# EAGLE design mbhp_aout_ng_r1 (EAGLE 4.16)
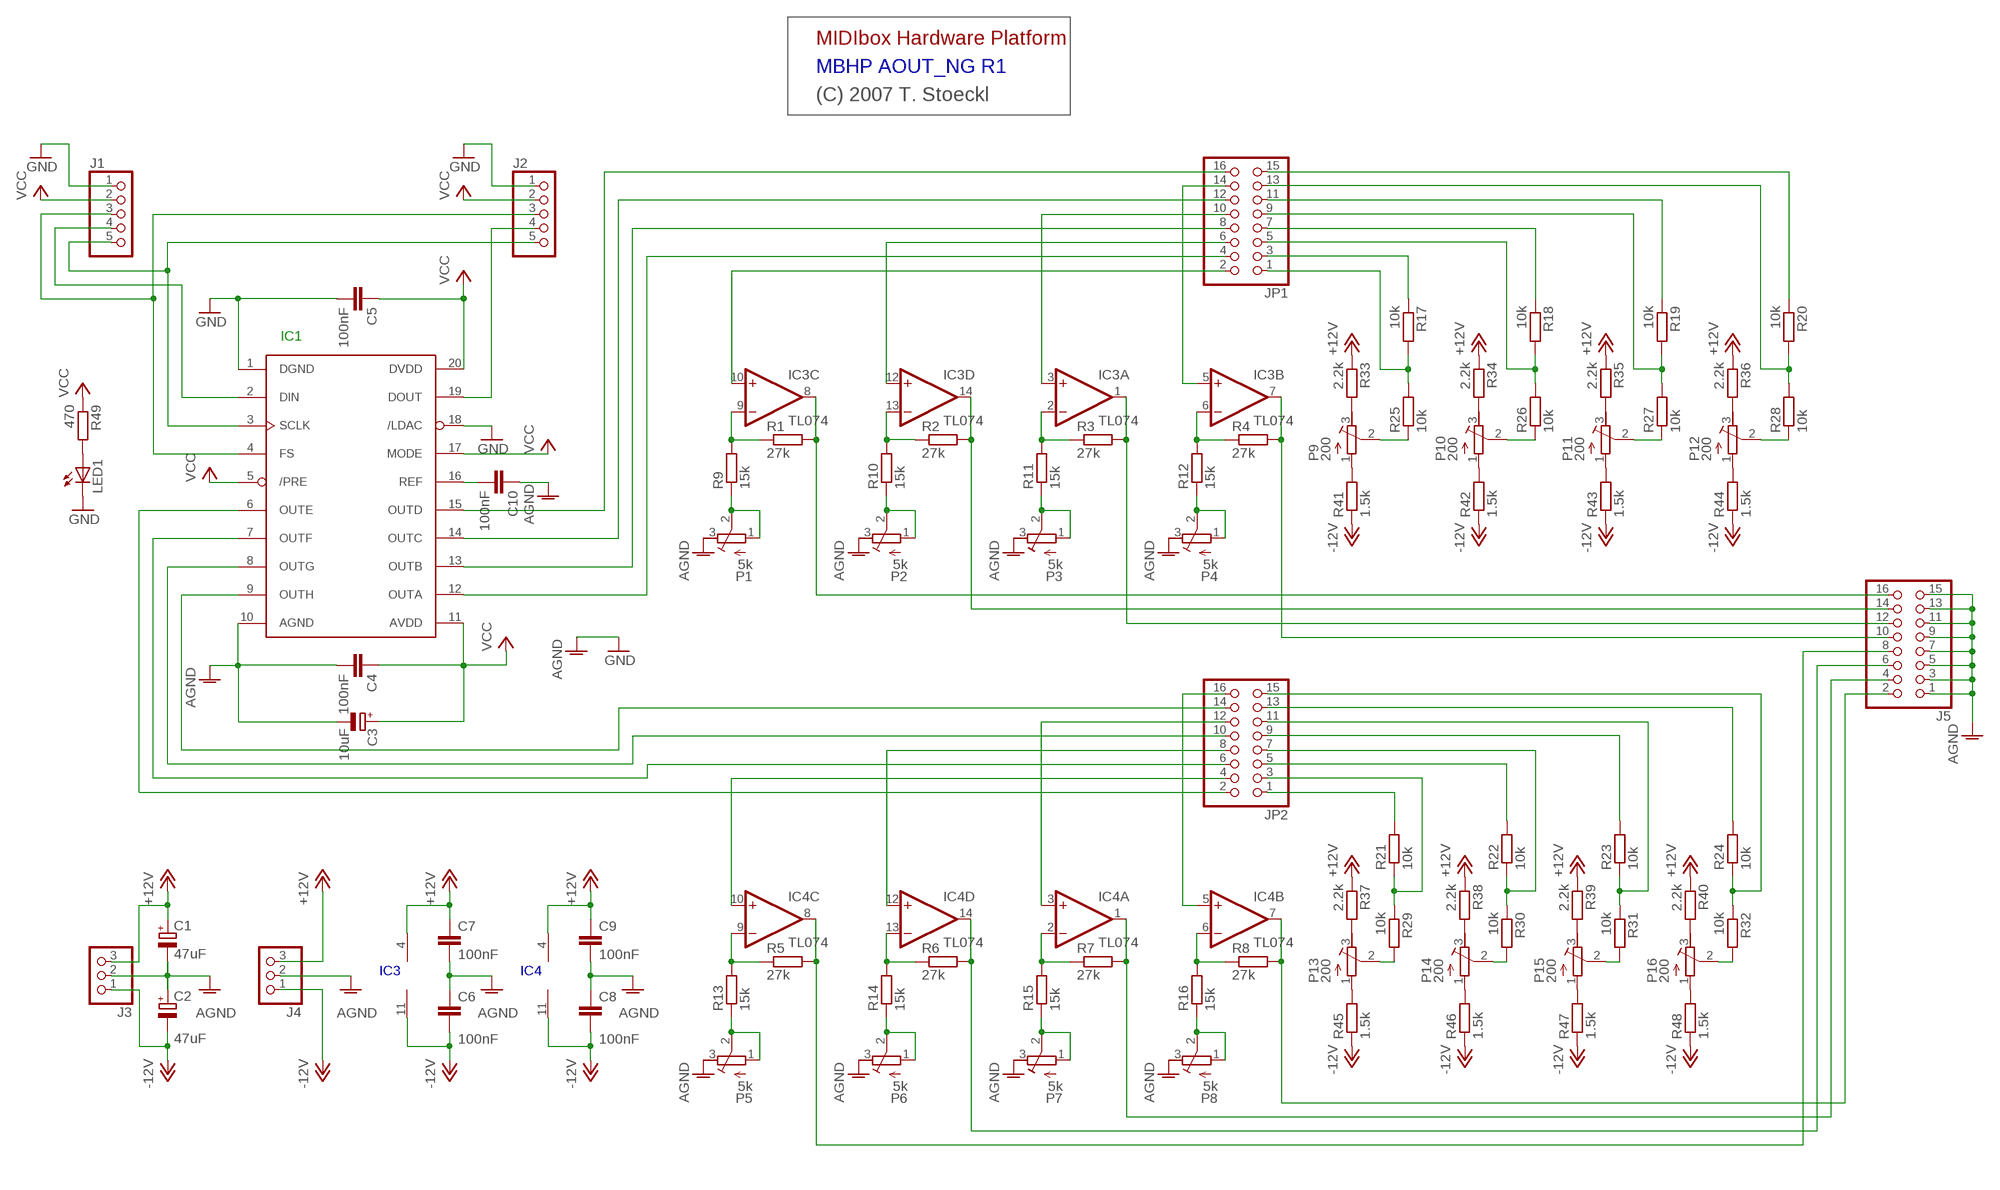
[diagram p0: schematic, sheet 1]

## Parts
C1  47uF  CPOL-EUE2-5  [E2-5]
C2  47uF  CPOL-EUE2-5  [E2-5]
C3  10uF  CPOL-EUE2.5-5  [E2,5-5]
C4  100nF  C2.5/2  [C2.5-2]
C5  100nF  C2.5/2  [C2.5-2]
C6  100nF  C2.5/2  [C2.5-2]
C7  100nF  C2.5/2  [C2.5-2]
C8  100nF  C2.5/2  [C2.5-2]
C9  100nF  C2.5/2  [C2.5-2]
C10  100nF  C2.5/2  [C2.5-2]
IC1  TLV5630  [SO20W]
IC3  TL074  TL074P  [DIL14]
IC4  TL074  TL074P  [DIL14]
J1  PINHD-1X5  [1X05]
J2  PINHD-1X5  [1X05]
J3  PINHD-1X3  [1X03]
J4  PINHD-1X3  [1X03]
J5  PINHD-2X8  [2X08]
JP1  PINHD-2X8  [2X08]
JP2  PINHD-2X8  [2X08]
LED1  LED3MM  [LED3MM]
P1  5k  R-TRIMM64Y  [RTRIM64Y]
P2  5k  R-TRIMM64Y  [RTRIM64Y]
P3  5k  R-TRIMM64Y  [RTRIM64Y]
P4  5k  R-TRIMM64Y  [RTRIM64Y]
P5  5k  R-TRIMM64Y  [RTRIM64Y]
P6  5k  R-TRIMM64Y  [RTRIM64Y]
P7  5k  R-TRIMM64Y  [RTRIM64Y]
P8  5k  R-TRIMM64Y  [RTRIM64Y]
P9  200  R-TRIMM64Y  [RTRIM64Y]
P10  200  R-TRIMM64Y  [RTRIM64Y]
P11  200  R-TRIMM64Y  [RTRIM64Y]
P12  200  R-TRIMM64Y  [RTRIM64Y]
P13  200  R-TRIMM64Y  [RTRIM64Y]
P14  200  R-TRIMM64Y  [RTRIM64Y]
P15  200  R-TRIMM64Y  [RTRIM64Y]
P16  200  R-TRIMM64Y  [RTRIM64Y]
R1  27k  R-EU_0207/2V  [0207/2V]
R2  27k  R-EU_0207/2V  [0207/2V]
R3  27k  R-EU_0207/2V  [0207/2V]
R4  27k  R-EU_0207/2V  [0207/2V]
R5  27k  R-EU_0207/2V  [0207/2V]
R6  27k  R-EU_0207/2V  [0207/2V]
R7  27k  R-EU_0207/2V  [0207/2V]
R8  27k  R-EU_0207/2V  [0207/2V]
R9  15k  R-EU_0207/2V  [0207/2V]
R10  15k  R-EU_0207/2V  [0207/2V]
R11  15k  R-EU_0207/2V  [0207/2V]
R12  15k  R-EU_0207/2V  [0207/2V]
R13  15k  R-EU_0207/2V  [0207/2V]
R14  15k  R-EU_0207/2V  [0207/2V]
R15  15k  R-EU_0207/2V  [0207/2V]
R16  15k  R-EU_0207/2V  [0207/2V]
R17  10k  R-EU_0207/2V  [0207/2V]
R18  10k  R-EU_0207/2V  [0207/2V]
R19  10k  R-EU_0207/2V  [0207/2V]
R20  10k  R-EU_0207/2V  [0207/2V]
R21  10k  R-EU_0207/2V  [0207/2V]
R22  10k  R-EU_0207/2V  [0207/2V]
R23  10k  R-EU_0207/2V  [0207/2V]
R24  10k  R-EU_0207/2V  [0207/2V]
R25  10k  R-EU_0207/2V  [0207/2V]
R26  10k  R-EU_0207/2V  [0207/2V]
R27  10k  R-EU_0207/2V  [0207/2V]
R28  10k  R-EU_0207/2V  [0207/2V]
R29  10k  R-EU_0207/2V  [0207/2V]
R30  10k  R-EU_0207/2V  [0207/2V]
R31  10k  R-EU_0207/2V  [0207/2V]
R32  10k  R-EU_0207/2V  [0207/2V]
R33  2.2k  R-EU_0207/2V  [0207/2V]
R34  2.2k  R-EU_0207/2V  [0207/2V]
R35  2.2k  R-EU_0207/2V  [0207/2V]
R36  2.2k  R-EU_0207/2V  [0207/2V]
R37  2.2k  R-EU_0207/2V  [0207/2V]
R38  2.2k  R-EU_0207/2V  [0207/2V]
R39  2.2k  R-EU_0207/2V  [0207/2V]
R40  2.2k  R-EU_0207/2V  [0207/2V]
R41  1.5k  R-EU_0207/2V  [0207/2V]
R42  1.5k  R-EU_0207/2V  [0207/2V]
R43  1.5k  R-EU_0207/2V  [0207/2V]
R44  1.5k  R-EU_0207/2V  [0207/2V]
R45  1.5k  R-EU_0207/2V  [0207/2V]
R46  1.5k  R-EU_0207/2V  [0207/2V]
R47  1.5k  R-EU_0207/2V  [0207/2V]
R48  1.5k  R-EU_0207/2V  [0207/2V]
R49  470  R-EU_0207/7  [0207/7]

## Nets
+12V: C1.+ C7.1 C9.1 IC3.4(P:V+) IC4.4(P:V+) J3.3 J4.3 R33.1 R34.1 R35.1 R36.1 R37.1 R38.1 R39.1 R40.1
-12V: C2.- C6.2 C8.2 IC3.11(P:V-) IC4.11(P:V-) J3.1 J4.1 R41.1 R42.1 R43.1 R44.1 R45.1 R46.1 R47.1 R48.1
AGND: C1.- C2.+ C3.- C4.2 C6.1 C7.2 C8.1 C9.2 C10.1 IC1.10(AGND) J3.2 J4.2 J5.1 J5.3 J5.5 J5.7 J5.9 J5.11 J5.13 J5.15 P1.3(A) P2.3(A) P3.3(A) P4.3(A) P5.3(A) P6.3(A) P7.3(A) P8.3(A)
GND: C5.2 IC1.1(DGND) IC1.18(/LDAC) J1.1 J2.1 LED1.K(C) ; supply symbol labelled AGND
N$1: JP1.3 R17.1
N$2: IC3.13(D:-IN) R2.1 R10.2
N$3: IC3.9(C:-IN) R1.1 R9.2
N$4: P9.1(E) R41.2
N$5: IC3.6(B:-IN) R4.1 R12.2
N$6: IC3.8(C:OUT) J5.16 R1.2
N$7: IC3.2(A:-IN) R3.1 R11.2
N$8: IC3.14(D:OUT) J5.14 R2.2
N$9: IC4.9(C:-IN) R5.1 R13.2
N$10: IC4.8(C:OUT) J5.8 R5.2
N$11: IC4.13(D:-IN) R6.1 R14.2
N$12: IC4.14(D:OUT) J5.6 R6.2
N$13: IC4.6(B:-IN) R8.1 R16.2
N$14: IC3.1(A:OUT) J5.12 R3.2
N$15: IC4.2(A:-IN) R7.1 R15.2
N$16: IC3.7(B:OUT) J5.10 R4.2
N$17: P2.1(E) P2.2(S) R10.1
N$18: P1.1(E) P1.2(S) R9.1
N$19: P4.1(E) P4.2(S) R12.1
N$20: P3.1(E) P3.2(S) R11.1
N$21: P5.1(E) P5.2(S) R13.1
N$22: P6.1(E) P6.2(S) R14.1
N$23: P8.1(E) P8.2(S) R16.1
N$24: P7.1(E) P7.2(S) R15.1
N$25: IC4.5(B:+IN) JP2.16
N$26: JP2.13 R24.2
N$27: JP2.15 R24.1 R32.1
N$28: P16.2(S) R32.2
N$29: IC1.12(OUTA) JP1.4
N$30: IC1.13(OUTB) JP1.8
N$31: IC4.3(A:+IN) JP2.12
N$32: JP2.9 R23.2
N$33: JP2.11 R23.1 R31.1
N$34: P15.2(S) R31.2
N$35: IC1.3(SCLK) J1.5 J2.5
N$36: IC4.12(D:+IN) JP2.8
N$37: JP2.5 R22.2
N$38: JP2.7 R22.1 R30.1
N$39: P14.2(S) R30.2
N$40: IC1.14(OUTC) JP1.12
N$41: IC4.10(C:+IN) JP2.4
N$42: JP2.3 R21.1 R29.1
N$43: P14.1(E) R46.2
N$44: P13.1(E) R45.2
N$45: IC1.15(OUTD) JP1.16
N$46: IC3.5(B:+IN) JP1.14
N$47: JP1.15 R20.1
N$48: JP1.13 R20.2 R28.2
N$49: P12.1(E) R44.2
N$50: IC1.6(OUTE) JP2.2
N$51: IC3.3(A:+IN) JP1.10
N$52: JP1.11 R19.1
N$53: JP1.9 R19.2 R27.2
N$54: P11.1(E) R43.2
N$56: IC3.12(D:+IN) JP1.6
N$57: JP1.7 R18.1
N$58: JP1.5 R18.2 R26.2
N$59: P10.2(S) R26.1
N$60: IC1.8(OUTG) JP2.10
N$61: IC3.10(C:+IN) JP1.2
N$62: JP2.1 R21.2
N$63: JP1.1 R17.2 R25.2
N$64: P9.2(S) R25.1
N$65: IC1.9(OUTH) JP2.14
N$66: IC1.2(DIN) J1.4
N$67: IC1.4(FS) J1.3 J2.3
N$68: P9.3(A) R33.2
N$69: IC4.7(B:OUT) J5.2 R8.2
N$70: IC4.1(A:OUT) J5.4 R7.2
N$71: P10.1(E) R42.2
N$72: P10.3(A) R34.2
N$73: P11.3(A) R35.2
N$74: P12.3(A) R36.2
N$75: P11.2(S) R27.1
N$76: IC1.19(DOUT) J2.4
N$77: P12.2(S) R28.1
N$78: C10.2 IC1.16(REF)
N$79: P13.2(S) R29.2
N$80: P13.3(A) R37.2
N$81: IC1.7(OUTF) JP2.6
N$85: P14.3(A) R38.2
N$86: P15.1(E) R47.2
N$87: P15.3(A) R39.2
N$88: P16.1(E) R48.2
N$89: P16.3(A) R40.2
N$95: LED1.A R49.2
VCC: C3.+ C4.1 C5.1 IC1.5(/PRE) IC1.11(AVDD) IC1.17(MODE) IC1.20(DVDD) J1.2 J2.2 R49.1

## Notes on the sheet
- MIDIbox Hardware Platform
- MBHP AOUT_NG R1
- (C) 2007 T. Stoeckl
- IC1
- IC3 | IC4
- .

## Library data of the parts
C1-C3 = rcl:CPOL-EU: POLARIZED CAPACITOR, European symbol
C4-C10 = capacitor-wima:C: CAPACITOR
IC1 = EigeneSammlung:TLV5630
IC3 IC4 = linear:TL074: OP AMP
J1 J2 = pinhead:PINHD-1X5: PIN HEADER
J3 J4 = pinhead:PINHD-1X3: PIN HEADER
J5 JP1 JP2 = pinhead:PINHD-2X8: PIN HEADER
LED1 = led:LED: LED
P1-P16 = rcl:R-TRIMM: Trimm resistor
R1-R49 = rcl:R-EU_: RESISTOR, European symbol

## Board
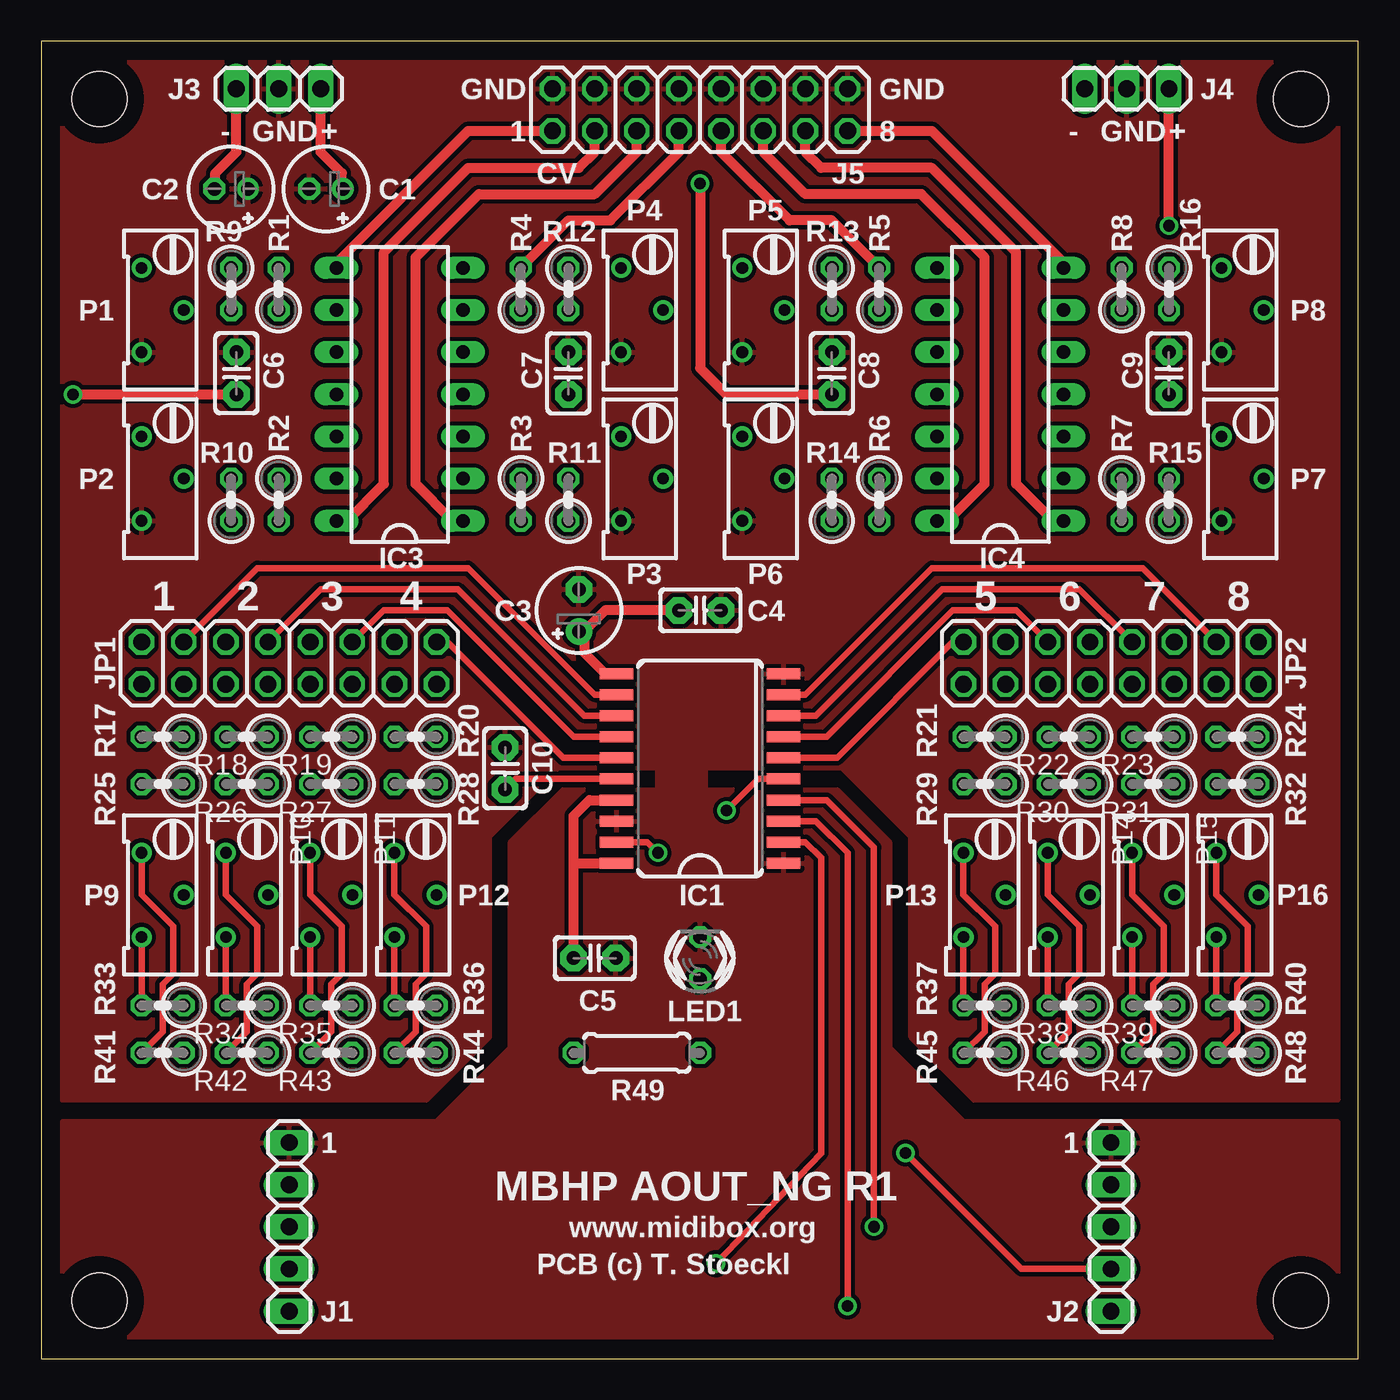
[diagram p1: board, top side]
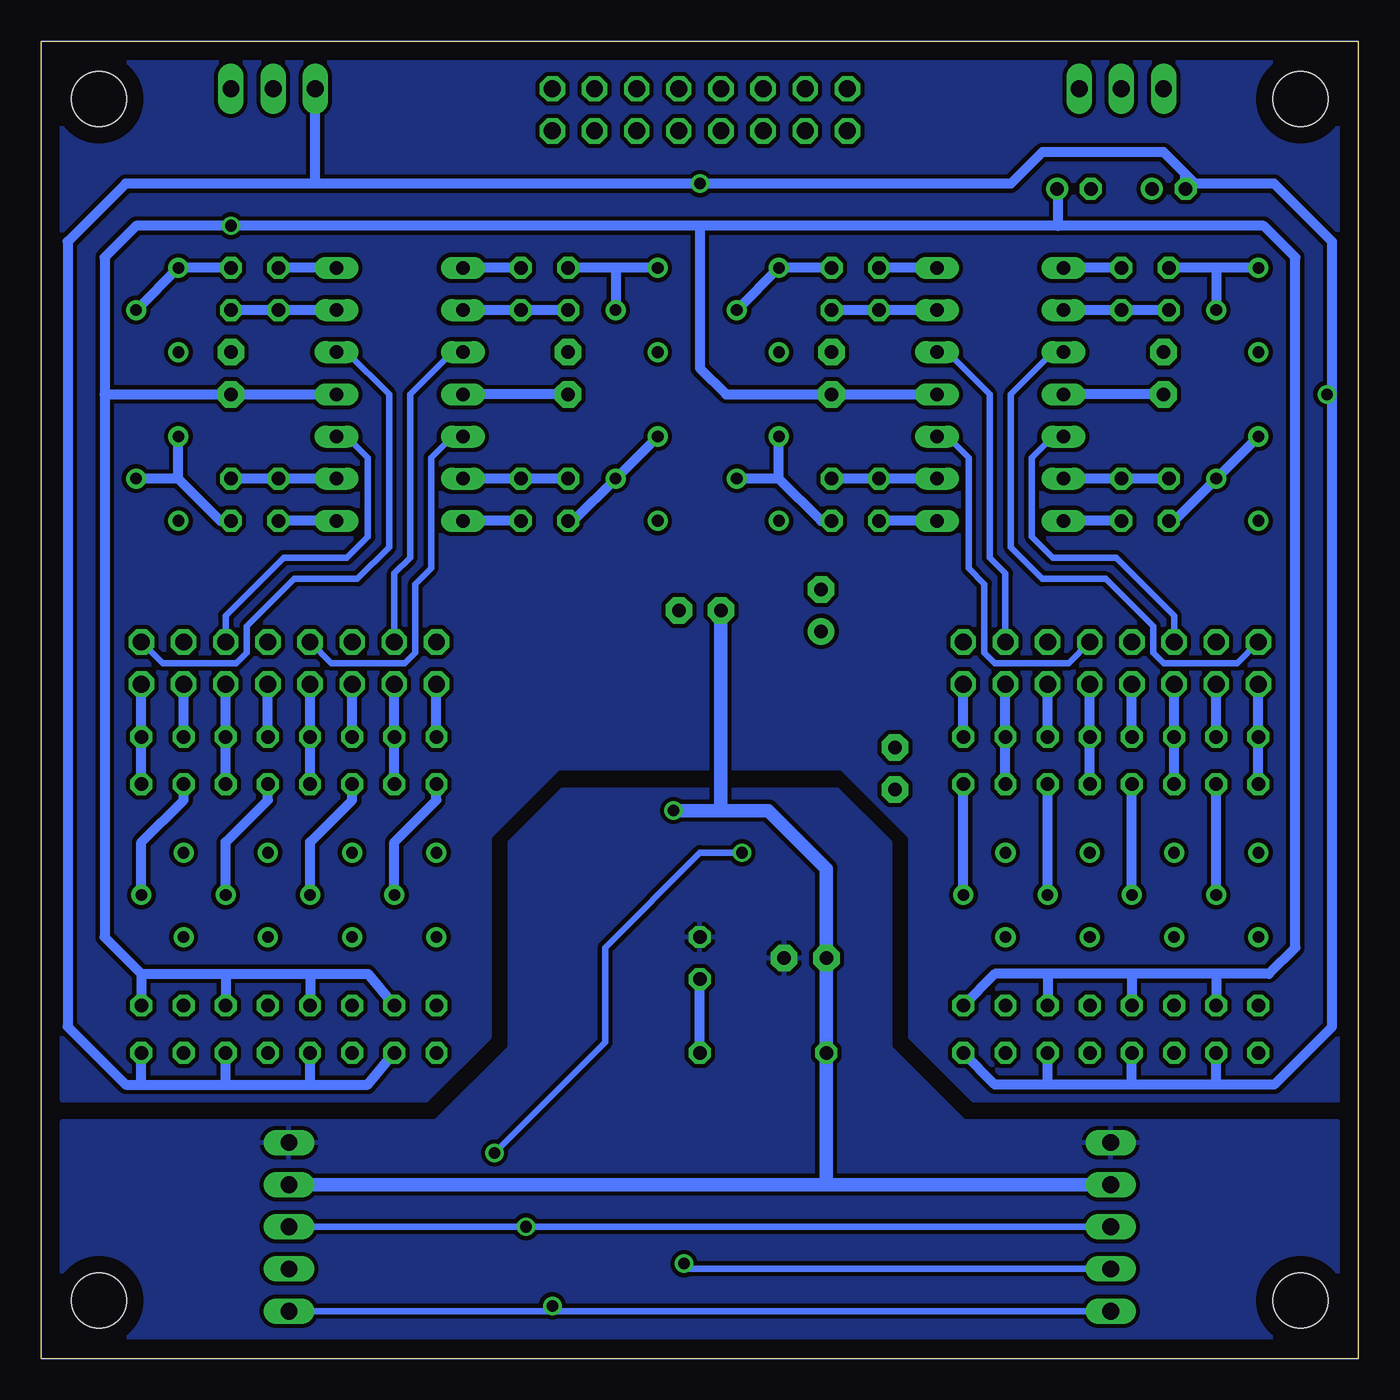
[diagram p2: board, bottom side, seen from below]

Size 79.36 x 79.37 mm. Coordinates in mm from the lower left corner, seen from the top.
Outline: 0,0 79.36,0 79.36,79.37 0,79.37 0,0
Copper layers (1*16): Top 0.035mm / dielectric 1.5mm / Bottom 0.035mm
Design rules "10mils": minimum track width 10mil, minimum drill 24mil, track to track 10mil, track to pad 10mil, pad to pad 10mil, via to via 10mil, smd to smd 10mil, copper to edge 40mil, drill to drill 10mil, minimum pad ring 10mil, minimum via ring 8mil, stop-mask expansion 0mil, vias tented up to drill 0mil, thermal gap 10mil
Holes 3.3 mm at 75.89,75.89 3.49,75.89 3.49,3.49 75.89,3.49

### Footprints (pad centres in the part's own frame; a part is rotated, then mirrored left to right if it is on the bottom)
E2-5 = drill 0.813 pad 1.27 round: + -1.016,0 | drill 0.813 pad 1.27 octagon: - 1.016,0
E2,5-5 = drill 0.813 pad 1.6 round: + -1.27,0 | drill 0.813 pad 1.6 octagon: - 1.27,0
C2.5-2 = drill 0.813 pad 1.6 octagon: 1 -1.27,0; 2 1.27,0
SO20W = smd 0.66 x 2.032: 1 -5.715,-5.029; 2 -4.445,-5.029; 3 -3.175,-5.029; 4 -1.905,-5.029; 5 -0.635,-5.029; 6 0.635,-5.029; 7 1.905,-5.029; 8 3.175,-5.029; 9 4.445,-5.029; 10 5.715,-5.029; 11 5.715,5.029; 12 4.445,5.029; 13 3.175,5.029; 14 1.905,5.029; 15 0.635,5.029; 16 -0.635,5.029; 17 -1.905,5.029; 18 -3.175,5.029; 19 -4.445,5.029; 20 -5.715,5.029
DIL14 = drill 0.813 long: 1 -7.62,-3.81; 2 -5.08,-3.81; 3 -2.54,-3.81; 4 0,-3.81; 5 2.54,-3.81; 6 5.08,-3.81; 7 7.62,-3.81; 8 7.62,3.81; 9 5.08,3.81; 10 2.54,3.81; 11 0,3.81; 12 -2.54,3.81; 13 -5.08,3.81; 14 -7.62,3.81
1X05 = drill 1.016 long: 1 -5.08,0; 2 -2.54,0; 3 0,0; 4 2.54,0; 5 5.08,0
1X03 = drill 1.016 long: 1 -2.54,0; 2 0,0; 3 2.54,0
2X08 = drill 1.016 octagon: 1 -8.89,-1.27; 2 -8.89,1.27; 3 -6.35,-1.27; 4 -6.35,1.27; 5 -3.81,-1.27; 6 -3.81,1.27; 7 -1.27,-1.27; 8 -1.27,1.27; 9 1.27,-1.27; 10 1.27,1.27; 11 3.81,-1.27; 12 3.81,1.27; 13 6.35,-1.27; 14 6.35,1.27; 15 8.89,-1.27; 16 8.89,1.27
LED3MM = drill 0.813 octagon: A -1.27,0; K 1.27,0
RTRIM64Y = drill 0.7 round: 1 0,-2.54; 2 -2.54,0; 3 0,2.54
0207/2V = drill 0.813 octagon: 1 -1.27,0; 2 1.27,0
0207/7 = drill 0.813 octagon: 1 -3.81,0; 2 3.81,0

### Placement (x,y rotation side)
C1  17.14,70.48 180 top
C2  11.43,70.48 180 top
C3  32.38,45.09 90 top
C4  39.69,45.09 0 top
C5  33.34,24.13 0 top
C6  11.75,59.37 270 top
C7  31.75,59.37 90 top
C8  47.62,59.37 270 top
C9  67.94,59.37 90 top
C10  27.94,35.56 270 top
IC1  39.69,35.56 90 top
IC3  21.59,58.1 90 top
IC4  57.78,58.1 90 top
J1  14.92,7.94 270 top
J2  64.45,7.94 270 top
J3  14.29,76.52 0 top
J4  65.41,76.52 0 top
J5  39.69,75.25 180 top
JP1  14.92,41.91 0 top
JP2  64.45,41.91 0 top
LED1  39.69,24.13 90 top
P1  6.03,63.18 180 top
P2  6.03,53.02 180 top
P3  34.92,53.02 180 top
P4  34.92,63.18 180 top
P5  42.23,63.18 180 top
P6  42.23,53.02 180 top
P7  71.12,53.02 180 top
P8  71.12,63.18 180 top
P9  6.03,27.94 180 top
P10  11.11,27.94 180 top
P11  16.19,27.94 180 top
P12  21.27,27.94 180 top
P13  55.56,27.94 180 top
P14  60.64,27.94 180 top
P15  65.72,27.94 180 top
P16  70.8,27.94 180 top
R1  14.29,64.45 90 top
R2  14.29,51.75 270 top
R3  28.89,51.75 270 top
R4  28.89,64.45 90 top
R5  50.48,64.45 90 top
R6  50.48,51.75 270 top
R7  65.09,51.75 270 top
R8  65.09,64.45 90 top
R9  11.43,64.45 270 top
R10  11.43,51.75 90 top
R11  31.75,51.75 90 top
R12  31.75,64.45 270 top
R13  47.62,64.45 270 top
R14  47.62,51.75 90 top
R15  67.94,51.75 90 top
R16  67.94,64.45 270 top
R17  7.3,37.47 180 top
R18  12.38,37.47 180 top
R19  17.46,37.47 180 top
R20  22.54,37.47 180 top
R21  56.83,37.47 180 top
R22  61.91,37.47 180 top
R23  66.99,37.47 180 top
R24  72.07,37.47 180 top
R25  7.3,34.61 180 top
R26  12.38,34.61 180 top
R27  17.46,34.61 180 top
R28  22.54,34.61 180 top
R29  56.83,34.61 180 top
R30  61.91,34.61 180 top
R31  66.99,34.61 180 top
R32  72.07,34.61 180 top
R33  7.3,21.27 180 top
R34  12.38,21.27 180 top
R35  17.46,21.27 180 top
R36  22.54,21.27 180 top
R37  56.83,21.27 180 top
R38  61.91,21.27 180 top
R39  66.99,21.27 180 top
R40  72.07,21.27 180 top
R41  7.3,18.41 180 top
R42  12.38,18.41 180 top
R43  17.46,18.41 180 top
R44  22.54,18.41 180 top
R45  56.83,18.41 180 top
R46  61.91,18.41 180 top
R47  66.99,18.41 180 top
R48  72.07,18.41 180 top
R49  35.88,18.41 0 top

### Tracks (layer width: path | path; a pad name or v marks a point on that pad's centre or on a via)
+12V  (via drill 0.7)
  Top 0.61: J3.3 16.83,72.71 18.1,71.44 18.1,70.48 C1.+ | v67.94,68.26 J4.3
  Bottom 0.61: 75.56,58.1 75.56,66.36 73.66,68.26 v67.94,68.26 39.69,68.26 | 75.56,58.1 C9.1 IC4.4 | 5.71,68.26 3.81,66.36 3.81,24.77 5.4,23.18 8.57,23.18 | 5.71,68.26 39.69,68.26 | 39.69,68.26 39.69,59.69 38.1,58.1 C7.1 IC3.4 | 8.57,23.18 13.65,23.18 | 13.65,23.18 18.73,23.18 | 8.57,23.18 R33.1 | 18.73,23.18 21.91,23.18 R36.1 | 18.73,23.18 R35.1 | 13.65,23.18 R34.1 | 75.56,58.1 75.56,25.4 73.34,23.18 | 73.34,23.18 68.26,23.18 | 68.26,23.18 63.18,23.18 | 63.18,23.18 59.69,23.18 R37.1 | 63.18,23.18 R38.1 | 68.26,23.18 R39.1 | 73.34,23.18 R40.1 | 5.71,68.26 18.1,68.26 18.1,70.48 C1.+
-12V  (via drill 0.7)
  Top 0.61: v39.69,70.8 39.69,59.69 41.27,58.1 C8.2 | v1.91,58.1 C6.2 | J3.1 11.75,72.71 10.48,71.44 10.48,70.48 C2.-
  Bottom 0.61: 1.59,58.1 1.59,67.31 5.08,70.8 9.84,70.8 | 62.87,70.8 v39.69,70.8 20.95,70.8 19.05,72.71 11.75,72.71 9.84,70.8 | 62.87,70.8 74.3,70.8 77.79,67.31 77.79,20 74.3,16.51 73.34,16.51 | 1.59,58.1 v1.91,58.1 | 1.59,58.1 1.59,20 5.08,16.51 8.57,16.51 | 8.57,16.51 R41.1 | 8.57,16.51 13.65,16.51 | 13.65,16.51 18.73,16.51 | 18.73,16.51 21.91,16.51 R44.1 | 18.73,16.51 R43.1 | 13.65,16.51 R42.1 | 73.34,16.51 68.26,16.51 | 68.26,16.51 63.18,16.51 | 63.18,16.51 59.69,16.51 R45.1 | 73.34,16.51 R48.1 | 68.26,16.51 R47.1 | 63.18,16.51 R46.1 | C8.2 IC4.11 | C6.2 IC3.11 | C2.- 10.48,70.48 10.48,71.44 10.16,70.8 9.84,70.8 | 62.87,70.8 J4.1
AGND
  pour Top (isolate 0.254): 78.11,15.56 56.2,15.56 52.39,19.37 52.39,31.43 48.26,35.56 40.01,35.56 40.01,34.29 37.15,34.29 37.15,35.56 31.11,35.56 26.99,31.43 26.99,19.37 23.18,15.56 1.27,15.56 1.27,78.11 78.11,78.11
GND
  Top 0.61: IC1.18 34.92,32.38
  pour Bottom (isolate 0.254): 78.11,1.27 78.11,14.29 55.56,14.29 51.12,18.73 51.12,31.11 47.94,34.29 31.43,34.29 28.26,31.11 28.26,18.73 23.81,14.29 1.27,14.29 1.27,1.27
  pour Top (isolate 0.254): 78.11,1.27 1.27,1.27 1.27,14.29 23.81,14.29 28.26,18.73 28.26,31.11 31.43,34.29 47.94,34.29 51.12,31.11 51.12,18.73 55.56,14.29 78.11,14.29
N$1
  Bottom 0.61: R17.1 JP1.3
N$2
  Bottom 0.61: IC3.13 R2.1 R10.2
N$3
  Bottom 0.61: IC3.9 R1.1 R9.2
N$4
  Top 0.406: R41.2 7.3,19.68 7.3,22.54 7.94,23.18 7.94,26.04 6.03,27.94 P9.1
N$5
  Bottom 0.61: IC3.6 R4.1 R12.2
N$6
  Top 0.61: IC3.8 17.78,66.04 25.72,73.98 J5.16
  Bottom 0.61: R1.2 IC3.8
N$7
  Bottom 0.61: IC3.2 R3.1 R11.2
N$8
  Top 0.61: IC3.14 18.41,50.48 20.64,52.7 20.64,66.67 25.72,71.75 32.38,71.75 33.34,72.71 J5.14
  Bottom 0.61: R2.2 IC3.14
N$9
  Bottom 0.61: IC4.9 R5.1 R13.2
N$10
  Top 0.61: J5.8 40.96,72.71 45.09,68.58 47.62,68.58 R5.2
  Bottom 0.61: R5.2 IC4.8
N$11
  Bottom 0.61: IC4.13 R6.1 R14.2
N$12
  Top 0.61: J5.6 43.5,72.71 46.04,70.17 53.02,70.17 56.83,66.36 56.83,52.7 54.61,50.48 IC4.14
  Bottom 0.61: R6.2 IC4.14
N$13
  Bottom 0.61: IC4.6 R8.1 R16.2
N$14
  Top 0.61: J5.12 35.88,72.71 33.34,70.17 26.35,70.17 22.54,66.36 22.54,52.7 24.77,50.48 IC3.1
  Bottom 0.61: IC3.1 R3.2
N$15
  Bottom 0.61: IC4.2 R7.1 R15.2
N$16
  Top 0.61: R4.2 31.75,68.58 34.29,68.58 38.42,72.71 J5.10
  Bottom 0.61: IC3.7 R4.2
N$17
  Bottom 0.61: R10.1 11.11,50.48 P2.2 P2.1
N$18
  Bottom 0.61: P1.1 8.57,65.72 | 8.57,65.72 R9.1 | 8.57,65.72 P1.2
N$19
  Bottom 0.61: R12.1 P4.1 P4.2
N$20
  Bottom 0.61: R11.1 32.38,50.48 34.92,53.02 | 34.92,53.02 P3.2 | 34.92,53.02 P3.1
N$21
  Bottom 0.61: P5.1 44.77,65.72 | 44.77,65.72 R13.1 | 44.77,65.72 P5.2
N$22
  Bottom 0.61: R14.1 47.31,50.48 P6.2 P6.1
N$23
  Bottom 0.61: P8.2 P8.1 R16.1
N$24
  Bottom 0.61: R15.1 68.58,50.48 71.12,53.02 | 71.12,53.02 P7.1 | 71.12,53.02 P7.2
N$25
  Bottom 0.406: IC4.5 60.96,60.64 58.42,58.1 58.42,48.9 60.33,46.99 64.14,46.99 66.99,44.13 66.99,42.55 67.63,41.91 72.07,41.91 JP2.16
N$26
  Bottom 0.61: R24.2 JP2.13
N$27
  Bottom 0.61: R32.1 R24.1 JP2.15
N$28
  Bottom 0.61: R32.2 70.8,33.66 73.34,31.11 P16.2
N$29
  Top 0.406: IC1.12 33.34,40.01 25.72,47.62 13.02,47.62 JP1.4
N$30
  Top 0.406: IC1.13 32.7,38.73 25.08,46.35 16.83,46.35 JP1.8
N$31
  Bottom 0.406: IC4.3 60.96,55.56 59.69,54.29 59.69,49.53 60.96,48.26 64.77,48.26 68.26,44.77 JP2.12
N$32
  Bottom 0.61: R23.2 JP2.9
N$33
  Bottom 0.61: R31.1 R23.1 JP2.11
N$34
  Bottom 0.61: R31.2 65.72,33.66 68.26,31.11 P15.2
N$35  (via drill 0.7)
  Top 0.406: 44.77,32.38 46.67,32.38 48.58,30.48 v48.58,3.17
  Top 0.61: 44.77,32.38 IC1.3
  Bottom 0.406: J1.5 48.58,2.86 | 48.58,2.86 v48.58,3.17 | 48.58,2.86 J2.5
N$36
  Bottom 0.406: IC4.12 54.61,55.56 55.88,54.29 55.88,47.62 56.83,46.67 56.83,42.55 57.47,41.91 61.91,41.91 JP2.8
N$37
  Bottom 0.61: R22.2 JP2.5
N$38
  Bottom 0.61: R30.1 R22.1 JP2.7
N$39
  Bottom 0.61: R30.2 60.64,33.66 63.18,31.11 P14.2
N$40
  Top 0.406: IC1.14 32.07,37.47 24.45,45.09 20.64,45.09 JP1.12
N$41
  Bottom 0.406: JP2.4 58.1,47.31 57.15,48.26 57.15,58.1 54.61,60.64 IC4.10
N$42
  Bottom 0.61: R29.1 R21.1 JP2.3
N$43
  Top 0.406: P14.1 60.64,27.94 62.55,26.04 62.55,23.18 61.91,22.54 61.91,19.68 R46.2
N$44
  Top 0.406: P13.1 55.56,27.94 57.47,26.04 57.47,23.18 56.83,22.54 56.83,19.68 R45.2
N$45
  Top 0.406: IC1.15 31.43,36.2 24.45,43.18 JP1.16
N$46
  Bottom 0.406: IC3.5 24.77,60.64 22.23,58.1 22.23,48.26 21.27,47.31 JP1.14
N$47
  Bottom 0.61: R20.1 JP1.15
N$48
  Bottom 0.61: R28.2 R20.2 JP1.13
N$49
  Top 0.406: P12.1 21.27,27.94 23.18,26.04 23.18,23.18 22.54,22.54 22.54,19.68 R44.2
N$50
  Top 0.406: IC1.6 47.94,36.2 54.93,43.18 JP2.2
N$51
  Bottom 0.406: IC3.3 24.77,55.56 23.5,54.29 23.5,47.62 22.54,46.67 22.54,42.55 21.91,41.91 17.46,41.91 JP1.10
N$52
  Bottom 0.61: R19.1 JP1.11
N$53
  Bottom 0.61: R19.2 16.19,37.15 | R27.2 R19.2 | R19.2 JP1.9
N$54
  Top 0.406: P11.1 16.19,27.94 18.1,26.04 18.1,23.18 17.46,22.54 17.46,19.68 R43.2
N$55
  Bottom 0: 0,79.37 79.36,79.37 79.36,0 0,0 0,79.37
N$56
  Bottom 0.406: IC3.12 18.41,55.56 19.68,54.29 19.68,49.53 18.41,48.26 14.61,48.26 11.11,44.77 JP1.6
N$57
  Bottom 0.61: R18.1 JP1.7
N$58
  Bottom 0.61: R26.2 R18.2 JP1.5
N$59
  Bottom 0.61: P10.2 R26.1
N$60
  Top 0.406: IC1.8 46.67,38.73 54.29,46.35 62.55,46.35 JP2.10
N$61
  Bottom 0.406: IC3.10 18.41,60.64 20.95,58.1 20.95,48.9 19.05,46.99 15.24,46.99 12.38,44.13 12.38,42.55 11.75,41.91 7.3,41.91 JP1.2
N$62
  Bottom 0.61: R21.2 JP2.1
N$63
  Bottom 0.61: R25.2 R17.2 JP1.1
N$64
  Bottom 0.61: P9.2 R25.1
N$65
  Top 0.406: IC1.9 46.04,40.01 53.66,47.62 66.36,47.62 JP2.14
N$66  (via drill 0.7)
  Top 0.406: IC1.2 46.04,31.11 46.99,30.16 46.99,12.38 v40.64,5.71
  Bottom 0.406: J1.4 40.32,5.4 v40.64,5.71
N$67  (via drill 0.7)
  Top 0.406: 44.77,33.66 47.31,33.66 50.16,30.8 v50.16,7.94
  Top 0.61: 44.77,33.66 IC1.4
  Bottom 0.406: J1.3 v50.16,7.94 J2.3
N$68
  Top 0.406: R33.2 P9.3
N$69
  Top 0.61: IC4.7 61.59,66.04 53.66,73.98 J5.2
  Bottom 0.61: IC4.7 R8.2
N$70
  Top 0.61: IC4.1 60.96,50.48 58.74,52.7 58.74,66.67 53.66,71.75 46.99,71.75 46.04,72.71 J5.4
  Bottom 0.61: IC4.1 R7.2
N$71
  Top 0.406: P10.1 11.11,27.94 13.02,26.04 13.02,23.18 12.38,22.54 12.38,19.68 R42.2
N$72
  Top 0.406: R34.2 P10.3
N$73
  Top 0.406: R35.2 P11.3
N$74
  Top 0.406: R36.2 P12.3
N$75
  Bottom 0.61: P11.2 R27.1
N$76  (via drill 0.7)
  Top 0.406: IC1.19 36.51,31.11 v37.15,30.48 | J2.4 59.05,5.4 v52.07,12.38
  Bottom 0.406: v37.15,30.48 39.69,30.48 45.4,24.77 45.4,19.05 v52.07,12.38
N$77
  Bottom 0.61: P12.2 R28.1
N$78
  Top 0.406: IC1.16 28.57,34.92 C10.2
N$79
  Bottom 0.61: R29.2 55.56,33.66 58.1,31.11 P13.2
N$80
  Top 0.406: R37.2 P13.3
N$81
  Top 0.406: IC1.7 47.31,37.47 54.93,45.09 58.74,45.09 JP2.6
N$85
  Top 0.406: R38.2 P14.3
N$86
  Top 0.406: P15.1 65.72,27.94 67.63,26.04 67.63,23.18 66.99,22.54 66.99,19.68 R47.2
N$87
  Top 0.406: R39.2 P15.3
N$88
  Top 0.406: P16.1 70.8,27.94 72.71,26.04 72.71,23.18 72.07,22.54 72.07,19.68 R48.2
N$89
  Top 0.406: R40.2 P16.3
N$95
  Bottom 0.61: R49.2 LED1.A
N$96
  pour Bottom (isolate 0.254): 1.27,15.56 23.18,15.56 26.99,19.37 26.99,31.43 31.11,35.56 48.26,35.56 52.39,31.43 52.39,19.37 56.2,15.56 78.11,15.56 78.11,74.3 74.3,74.3 74.3,78.11 5.08,78.11 5.08,74.3 1.27,74.3
VCC  (via drill 0.7)
  Top 0.406: v41.27,33.02 43.18,34.92 IC1.5 44.77,34.92
  Top 0.61: 35.24,41.27 IC1.11 33.97,41.27 32.7,42.55 32.7,43.81 | C5.1 32.07,29.84 | 32.07,29.84 IC1.20 | 34.61,33.66 IC1.17 33.02,33.66 32.07,32.7 32.07,29.84 | C4.1 33.97,45.09 32.7,43.81 | 32.7,43.81 C3.+
  Bottom 0.813: 38.42,33.02 v41.27,33.02 | 38.42,33.02 35.56,33.02 32.07,29.53 C5.1 R49.1 32.07,10.48 | 38.42,33.02 C4.1 | J1.2 32.07,10.48 | 32.07,10.48 J2.2

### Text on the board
tPlace: - | - | 1 | 2 | 3 | 4 | 5 | 6 | 7 | 8
tNames: GND | GND | 1 | GND | + | 8 | GND | + | CV | 1 | 1 | MBHP AOUT_NG R1 | www.midibox.org | PCB (c) T. Stoeckl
